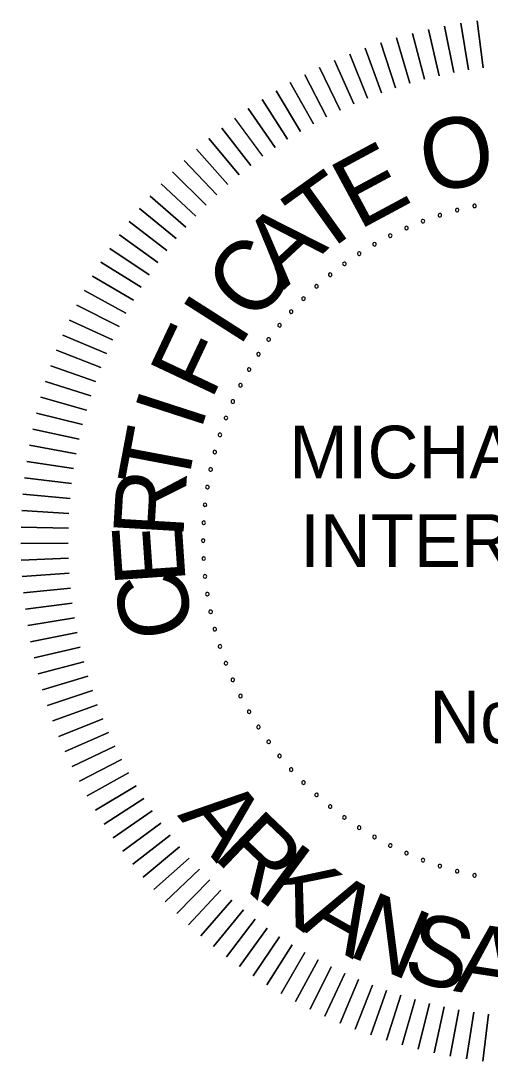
# Model space of a CAD drawing. Extents: x 166 to 3406, y 71 to 2074.
# Drawn here: x 2779.4 to 2890.7, y 403.9 to 650.8 of the extents above; entities that cross this region are included whole.
import ezdxf

# ---------------------------------------------------------------- set-up
doc = ezdxf.new("R2010")
doc.units = 0
doc.layers.add('G-ANNO-TEXT', color=7, linetype='Continuous')

msp = doc.modelspace()

# ---------------------------------------------------------------- linework, layer by layer
at = {"layer": 'G-ANNO-TEXT'}
for points in [[(2882.04, 638.5), (2879.87, 649.52)], [(2879.87, 649.52), (2882.04, 638.5)], [(2885.54, 639.14), (2883.72, 650.21)], [(2883.72, 650.21), (2885.54, 639.14)], [(2889.05, 639.66), (2887.59, 650.78)], [(2887.59, 650.78), (2889.05, 639.66)], [(2875.1, 636.91), (2872.25, 647.77)], [(2872.25, 647.77), (2875.1, 636.91)], [(2878.56, 637.76), (2876.05, 648.7)], [(2876.05, 648.7), (2878.56, 637.76)], [(2868.28, 634.89), (2864.76, 645.55)], [(2864.76, 645.55), (2868.28, 634.89)], [(2871.68, 635.96), (2868.49, 646.72)], [(2868.49, 646.72), (2871.68, 635.96)], [(2861.6, 632.45), (2857.42, 642.86)], [(2857.42, 642.86), (2861.6, 632.45)], [(2864.93, 633.72), (2861.06, 644.26)], [(2861.06, 644.26), (2864.93, 633.72)], [(2855.09, 629.58), (2850.26, 639.71)], [(2850.26, 639.71), (2855.09, 629.58)], [(2858.33, 631.07), (2853.81, 641.34)], [(2853.81, 641.34), (2858.33, 631.07)], [(2851.91, 628), (2846.76, 637.97)], [(2846.76, 637.97), (2851.91, 628)], [(2848.77, 626.32), (2843.31, 636.12)], [(2843.31, 636.12), (2848.77, 626.32)], [(2842.67, 622.67), (2836.61, 632.11)], [(2836.61, 632.11), (2842.67, 622.67)], [(2845.69, 624.54), (2839.93, 634.17)], [(2839.93, 634.17), (2845.69, 624.54)], [(2839.71, 620.7), (2833.35, 629.94)], [(2833.35, 629.94), (2839.71, 620.7)], [(2836.81, 618.63), (2830.16, 627.68)], [(2833.98, 616.48), (2827.05, 625.31)], [(2827.05, 625.31), (2833.98, 616.48)], [(2831.22, 614.24), (2824.01, 622.85)], [(2824.01, 622.85), (2831.22, 614.24)], [(2828.52, 611.92), (2821.06, 620.3)], [(2821.06, 620.3), (2828.52, 611.92)], [(2825.91, 609.51), (2818.18, 617.65)], [(2818.18, 617.65), (2825.91, 609.51)], [(2823.37, 607.02), (2815.39, 614.91)], [(2815.39, 614.91), (2823.37, 607.02)], [(2820.91, 604.45), (2812.68, 612.09)], [(2812.68, 612.09), (2820.91, 604.45)], [(2818.53, 601.81), (2810.07, 609.18)], [(2810.07, 609.18), (2818.53, 601.81)], [(2816.23, 599.09), (2807.55, 606.2)], [(2807.55, 606.2), (2816.23, 599.09)], [(2814.02, 596.3), (2805.12, 603.13)], [(2805.12, 603.13), (2814.02, 596.3)], [(2811.9, 593.45), (2802.79, 599.99)], [(2802.79, 599.99), (2811.9, 593.45)], [(2809.88, 590.53), (2800.56, 596.78)], [(2800.56, 596.78), (2809.88, 590.53)], [(2807.94, 587.54), (2798.43, 593.5)], [(2798.43, 593.5), (2807.94, 587.54)], [(2806.1, 584.5), (2796.41, 590.16)], [(2796.41, 590.16), (2806.1, 584.5)], [(2804.35, 581.4), (2794.49, 586.75)], [(2794.49, 586.75), (2804.35, 581.4)], [(2802.71, 578.25), (2792.68, 583.29)], [(2792.68, 583.29), (2802.71, 578.25)], [(2801.16, 575.05), (2790.98, 579.77)], [(2790.98, 579.77), (2801.16, 575.05)], [(2799.71, 571.8), (2789.39, 576.2)], [(2789.39, 576.2), (2799.71, 571.8)], [(2798.37, 568.5), (2787.91, 572.58)], [(2787.91, 572.58), (2798.37, 568.5)], [(2797.13, 565.17), (2786.55, 568.91)], [(2786.55, 568.91), (2797.13, 565.17)], [(2796, 561.8), (2785.31, 565.21)], [(2785.31, 565.21), (2796, 561.8)], [(2794.97, 558.39), (2784.18, 561.46)], [(2784.18, 561.46), (2794.97, 558.39)], [(2794.05, 554.96), (2783.17, 557.69)], [(2783.17, 557.69), (2794.05, 554.96)], [(2793.24, 551.49), (2782.28, 553.88)], [(2782.28, 553.88), (2793.24, 551.49)], [(2792.54, 548.01), (2781.5, 550.05)], [(2781.5, 550.05), (2792.54, 548.01)], [(2791.95, 544.5), (2780.85, 546.19)], [(2780.85, 546.19), (2791.95, 544.5)], [(2791.47, 540.98), (2780.32, 542.32)], [(2780.32, 542.32), (2791.47, 540.98)], [(2791.1, 537.44), (2779.92, 538.43)], [(2779.92, 538.43), (2791.1, 537.44)], [(2790.84, 533.89), (2779.63, 534.53)], [(2779.63, 534.53), (2790.84, 533.89)], [(2790.69, 530.34), (2779.47, 530.63)], [(2779.47, 530.63), (2790.69, 530.34)], [(2790.65, 526.78), (2779.43, 526.72)], [(2779.43, 526.72), (2790.65, 526.78)], [(2790.73, 523.22), (2779.51, 522.81)], [(2779.51, 522.81), (2790.73, 523.22)], [(2790.92, 519.67), (2779.72, 518.91)], [(2779.72, 518.91), (2790.92, 519.67)], [(2791.21, 516.13), (2780.05, 515.01)], [(2780.05, 515.01), (2791.21, 516.13)], [(2791.62, 512.6), (2780.5, 511.13)], [(2780.5, 511.13), (2791.62, 512.6)], [(2792.15, 509.08), (2781.07, 507.26)], [(2781.07, 507.26), (2792.15, 509.08)], [(2792.78, 505.58), (2781.76, 503.41)], [(2781.76, 503.41), (2792.78, 505.58)], [(2793.52, 502.1), (2782.58, 499.59)], [(2782.58, 499.59), (2793.52, 502.1)], [(2794.37, 498.64), (2783.51, 495.79)], [(2783.51, 495.79), (2794.37, 498.64)], [(2795.32, 495.22), (2784.56, 492.03)], [(2784.56, 492.03), (2795.32, 495.22)], [(2796.39, 491.83), (2785.74, 488.3)], [(2785.74, 488.3), (2796.39, 491.83)], [(2797.56, 488.47), (2787.02, 484.61)], [(2787.02, 484.61), (2797.56, 488.47)], [(2798.84, 485.15), (2788.42, 480.96)], [(2788.42, 480.96), (2798.84, 485.15)], [(2800.21, 481.87), (2789.94, 477.35)], [(2789.94, 477.35), (2800.21, 481.87)], [(2801.7, 478.64), (2791.57, 473.8)], [(2791.57, 473.8), (2801.7, 478.64)], [(2803.28, 475.45), (2793.31, 470.3)], [(2793.31, 470.3), (2803.28, 475.45)], [(2804.96, 472.32), (2795.16, 466.85)], [(2795.16, 466.85), (2804.96, 472.32)], [(2806.74, 469.24), (2797.11, 463.47)], [(2797.11, 463.47), (2806.74, 469.24)], [(2808.62, 466.21), (2799.17, 460.15)], [(2799.17, 460.15), (2808.62, 466.21)], [(2810.58, 463.25), (2801.34, 456.89)], [(2801.34, 456.89), (2810.58, 463.25)], [(2812.65, 460.35), (2803.6, 453.71)], [(2803.6, 453.71), (2812.65, 460.35)], [(2814.8, 457.52), (2805.97, 450.59)], [(2805.97, 450.59), (2814.8, 457.52)], [(2817.04, 454.76), (2808.43, 447.56)], [(2808.43, 447.56), (2817.04, 454.76)], [(2819.36, 452.07), (2810.98, 444.6)], [(2810.98, 444.6), (2819.36, 452.07)], [(2821.77, 449.45), (2813.63, 441.72)], [(2813.63, 441.72), (2821.77, 449.45)], [(2824.26, 446.91), (2816.37, 438.93)], [(2816.37, 438.93), (2824.26, 446.91)], [(2826.83, 444.45), (2819.19, 436.22)], [(2819.19, 436.22), (2826.83, 444.45)], [(2822.1, 433.61), (2829.47, 442.07)], [(2829.47, 442.07), (2822.1, 433.61)], [(2825.08, 431.09), (2832.19, 439.77)], [(2832.19, 439.77), (2825.08, 431.09)], [(2828.15, 428.66), (2834.98, 437.57)], [(2834.98, 437.57), (2828.15, 428.66)], [(2831.29, 426.33), (2837.83, 435.45)], [(2837.83, 435.45), (2831.29, 426.33)], [(2834.5, 424.1), (2840.75, 433.42)], [(2840.75, 433.42), (2834.5, 424.1)], [(2837.78, 421.97), (2843.74, 431.48)], [(2843.74, 431.48), (2837.78, 421.97)], [(2841.12, 419.95), (2846.78, 429.64)], [(2846.78, 429.64), (2841.12, 419.95)], [(2844.53, 418.03), (2849.88, 427.89)], [(2849.88, 427.89), (2844.53, 418.03)], [(2847.99, 416.22), (2853.03, 426.25)], [(2853.03, 426.25), (2847.99, 416.22)], [(2851.51, 414.52), (2856.24, 424.7)], [(2856.24, 424.7), (2851.51, 414.52)], [(2855.09, 412.93), (2859.48, 423.26)], [(2859.48, 423.26), (2855.09, 412.93)], [(2858.71, 411.46), (2862.78, 421.91)], [(2862.78, 421.91), (2858.71, 411.46)], [(2862.37, 410.09), (2866.11, 420.67)], [(2866.11, 420.67), (2862.37, 410.09)], [(2866.08, 408.85), (2869.48, 419.54)], [(2869.48, 419.54), (2866.08, 408.85)], [(2869.82, 407.72), (2872.89, 418.51)], [(2872.89, 418.51), (2869.82, 407.72)], [(2873.59, 406.71), (2876.32, 417.59)], [(2876.32, 417.59), (2873.59, 406.71)], [(2877.4, 405.82), (2879.79, 416.78)], [(2879.79, 416.78), (2877.4, 405.82)], [(2881.23, 405.05), (2883.27, 416.08)], [(2883.27, 416.08), (2881.23, 405.05)], [(2885.09, 404.4), (2886.78, 415.49)], [(2886.78, 415.49), (2885.09, 404.4)], [(2888.96, 403.87), (2890.31, 415.01)], [(2890.31, 415.01), (2888.96, 403.87)]]:
    msp.add_lwpolyline(points, dxfattribs=at)
for centre, start, end in [((2878.77, 604.65), 18, 198), ((2882.85, 605.86), 15, 195), ((2882.85, 605.86), 195, 15), ((2886.98, 606.85), 12, 192), ((2886.98, 606.85), 192, 12), ((2874.76, 603.23), 21, 201), ((2874.76, 603.23), 201, 21), ((2878.77, 604.65), 198, 18), ((2867, 599.77), 27, 207), ((2870.84, 601.6), 24, 204), ((2870.84, 601.6), 204, 24), ((2863.26, 597.75), 30, 210), ((2863.26, 597.75), 210, 30), ((2867, 599.77), 207, 27), ((2859.64, 595.52), 33, 213), ((2859.64, 595.52), 213, 33), ((2856.13, 593.12), 36, 216), ((2856.13, 593.12), 216, 36), ((2852.76, 590.53), 39, 219), ((2852.76, 590.53), 219, 39), ((2849.53, 587.77), 42, 222), ((2849.53, 587.77), 222, 42), ((2846.44, 584.84), 45, 225), ((2846.44, 584.84), 225, 45), ((2843.52, 581.75), 48, 228), ((2843.52, 581.75), 228, 48), ((2840.75, 578.52), 51, 231), ((2840.75, 578.52), 231, 51), ((2838.17, 575.15), 54, 234), ((2838.17, 575.15), 234, 54), ((2835.76, 571.64), 57, 237), ((2835.76, 571.64), 237, 57), ((2833.54, 568.02), 60, 240), ((2833.54, 568.02), 240, 60), ((2831.51, 564.28), 63, 243), ((2831.51, 564.28), 243, 63), ((2829.68, 560.44), 66, 246), ((2829.68, 560.44), 246, 66), ((2828.05, 556.52), 69, 249), ((2828.05, 556.52), 249, 69), ((2826.63, 552.51), 72, 252), ((2826.63, 552.51), 252, 72), ((2825.42, 548.43), 75, 255), ((2825.42, 548.43), 255, 75), ((2824.43, 544.3), 78, 258), ((2824.43, 544.3), 258, 78), ((2823.65, 540.12), 81, 261), ((2823.65, 540.12), 261, 81), ((2823.1, 535.9), 84, 264), ((2823.1, 535.9), 264, 84), ((2822.77, 531.66), 87, 267), ((2822.77, 531.66), 267, 87), ((2822.65, 527.41), 90, 270), ((2822.65, 527.41), 270, 90), ((2822.77, 523.16), 93, 273), ((2822.77, 523.16), 273, 93), ((2823.1, 518.92), 96, 276), ((2823.1, 518.92), 276, 96), ((2823.65, 514.71), 99, 279), ((2823.65, 514.71), 279, 99), ((2824.43, 510.53), 102, 282), ((2824.43, 510.53), 282, 102), ((2825.42, 506.39), 105, 285), ((2825.42, 506.39), 285, 105), ((2826.63, 502.31), 108, 288), ((2826.63, 502.31), 288, 108), ((2828.05, 498.31), 111, 291), ((2828.05, 498.31), 291, 111), ((2829.68, 494.38), 114, 294), ((2829.68, 494.38), 294, 114), ((2831.51, 490.54), 117, 297), ((2831.51, 490.54), 297, 117), ((2833.54, 486.8), 120, 300), ((2833.54, 486.8), 300, 120), ((2835.76, 483.18), 123, 303), ((2835.76, 483.18), 303, 123), ((2838.17, 479.67), 126, 306), ((2838.17, 479.67), 306, 126), ((2840.75, 476.3), 129, 309), ((2840.75, 476.3), 309, 129), ((2843.52, 473.07), 132, 312), ((2843.52, 473.07), 312, 132), ((2846.44, 469.98), 135, 315), ((2846.44, 469.98), 315, 135), ((2849.53, 467.06), 138, 318), ((2849.53, 467.06), 318, 138), ((2852.76, 464.3), 141, 321), ((2852.76, 464.3), 321, 141), ((2856.13, 461.71), 144, 324), ((2856.13, 461.71), 324, 144), ((2859.64, 459.3), 147, 327), ((2859.64, 459.3), 327, 147), ((2863.26, 457.08), 150, 330), ((2863.26, 457.08), 330, 150), ((2867, 455.05), 153, 333), ((2867, 455.05), 333, 153), ((2870.84, 453.22), 156, 336), ((2870.84, 453.22), 336, 156), ((2874.76, 451.59), 339, 159), ((2874.76, 451.59), 159, 339), ((2878.77, 450.17), 162, 342), ((2878.77, 450.17), 342, 162), ((2882.85, 448.96), 165, 345), ((2882.85, 448.96), 345, 165), ((2886.98, 447.97), 168, 348), ((2886.98, 447.97), 348, 168)]:
    msp.add_arc(centre, 0.417, start, end, dxfattribs=at)

# ---------------------------------------------------------------- texts
for s, rotation, p in [('O', 10.7295, (2875.71, 609.74)), ('E', 28.279, (2859.53, 601.01)), ('T', 35.5725, (2850.22, 594.55)), ('A', 42.8659, (2841.76, 586.85)), ('C', 50.1594, (2834.75, 578.52)), ('I', 57.4529, (2831.12, 572.95)), ('F', 64.7464, (2824.58, 560.48)), ('I', 72.0398, (2822, 553.16)), ('T', 79.3333, (2818.69, 538.8)), ('R', 86.6268, (2817.92, 527.78)), ('E', 93.9203, (2818.54, 517.37)), ('C', 101.2137, (2820.67, 505.78)), ('A', 309.5859, (2816.4, 462.15)), ('R', 316.3356, (2824.68, 452.32)), ('K', 323.6428, (2834.88, 442.86)), ('A', 330.3925, (2845.29, 435.33)), ('N', 337.1422, (2856.52, 429.09)), ('S', 344.4494, (2869.41, 423.86)), ('A', 351.1991, (2881.82, 420.53))]:
    msp.add_text(s, height=16.67, rotation=rotation, dxfattribs=at).set_placement(p)
for s, height, p in [('MICHAEL BAKER', 12.5016, (2843.04, 542.19)), (' INTERNATIONAL', 12.5016, (2841.03, 521.17)), (' No. 1126', 12.502, (2871.6, 479.31))]:
    msp.add_text(s, height=height, dxfattribs=at).set_placement(p)

doc.saveas('drawing.dxf')
